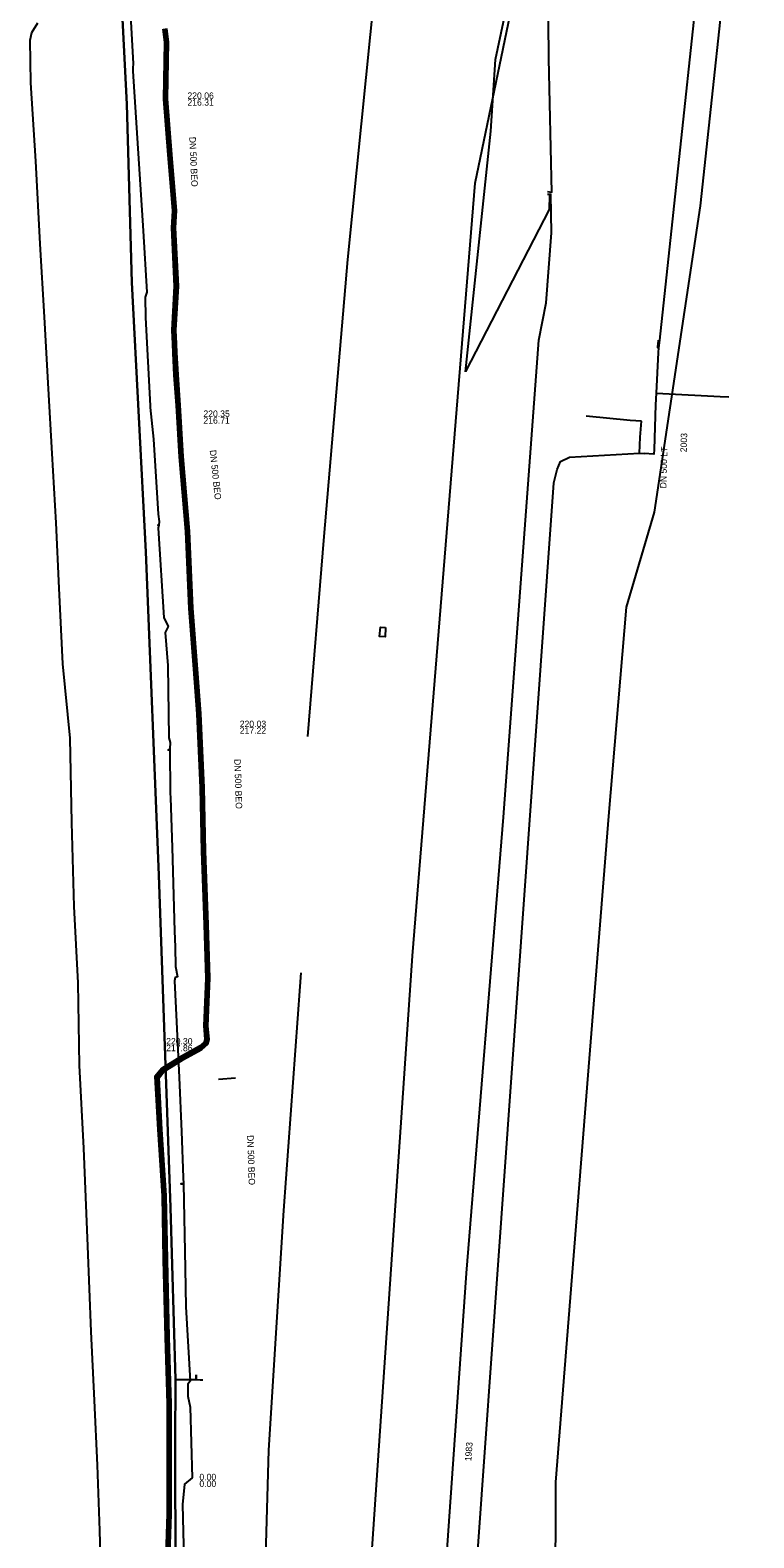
# Model space of a CAD drawing. Extents: x -599951 to -598963, y -1164095 to -1162939.
# Drawn here: x -599221.2 to -599131.5, y -1163894.1 to -1163707.4 of the extents above; entities that cross this region are included whole.
import ezdxf

# ---------------------------------------------------------------- set-up
doc = ezdxf.new("R2010")
doc.units = 0
for name, color, linetype in [('Level 1', 7, 'Continuous'), ('Level 3', 7, 'Continuous'), ('Vrstva 12', 7, 'Continuous'), ('Vrstva 13', 7, 'Continuous'), ('Vrstva 15', 7, 'Continuous'), ('Vrstva 42', 7, 'Continuous'), ('Vrstva 44', 7, 'Continuous'), ('Vrstva 55', 7, 'Continuous'), ('Vrstva 58', 7, 'Continuous'), ('Vrstva 9', 7, 'Continuous')]:
    doc.layers.add(name, color=color, linetype=linetype)

msp = doc.modelspace()

# ---------------------------------------------------------------- linework, layer by layer
at = {"layer": 'Level 1'}
for points in [[(-599173.8, -1163822.04), (-599166.01, -1163726.36), (-599144.8, -1163624.27), (-599116.33, -1163540.56), (-599088.36, -1163467.42), (-599053.62, -1163407.24), (-599018.44, -1163353.97), (-598979.36, -1163301.03), (-598963.215, -1163275.716)], [(-599189.994, -1164094.695), (-599188.19, -1164033.79), (-599173.8, -1163822.04)]]:
    msp.add_lwpolyline(points, dxfattribs=at)
at = {"layer": 'Level 3'}
msp.add_lwpolyline([(-599177.14, -1163781.39), (-599177.141, -1163781.419), (-599177.195, -1163782.524), (-599177.89, -1163782.49), (-599177.77, -1163781.36)], close=True, dxfattribs=at)
at = {"layer": 'Vrstva 13'}
for p, q in [((-599143.395, -1163746.537), (-599143.368, -1163746.3)), ((-599143.368, -1163746.3), (-599143.314, -1163745.805)), ((-599145.593, -1163757.802), (-599145.419, -1163755.84)), ((-599145.678, -1163759.782), (-599145.593, -1163757.802))]:
    msp.add_line(p, q, dxfattribs=at)
for points in [[(-599136.279, -1163681.357), (-599143.211, -1163745.819), (-599143.303, -1163746.751), (-599143.341, -1163747.337)], [(-599143.341, -1163747.337), (-599143.603, -1163752.362), (-599143.68, -1163753.83), (-599143.836, -1163759.328), (-599143.884, -1163759.926), (-599145.08, -1163759.83)], [(-599143.303, -1163746.751), (-599143.415, -1163746.741), (-599143.395, -1163746.537)], [(-599143.603, -1163752.362), (-599142.788, -1163752.405), (-599135.657, -1163752.781), (-599134.612, -1163752.841)], [(-599145.419, -1163755.84), (-599146.829, -1163755.755), (-599152.276, -1163755.203)], [(-599172.525, -1163991.426), (-599156.29, -1163763.465), (-599155.884, -1163761.839), (-599155.477, -1163760.823), (-599154.329, -1163760.314), (-599145.678, -1163759.782), (-599145.08, -1163759.83)]]:
    msp.add_lwpolyline(points, dxfattribs=at)
at = {"layer": 'Vrstva 42'}
for points in [[(-599211.757, -1163588.838), (-599211.66, -1163589.578), (-599212.89, -1163589.29), (-599214.35, -1163588.59), (-599214.49, -1163593.34), (-599213.28, -1163609.58), (-599212.1, -1163632.7), (-599211.89, -1163651.61), (-599210.7, -1163669.15), (-599209.68, -1163696.63), (-599210.04, -1163699.48), (-599209.19, -1163716.57), (-599208.58, -1163738.66), (-599206.82, -1163772.03), (-599205.21, -1163812.07), (-599203.78, -1163853.21), (-599203.16, -1163874.53), (-599200.61, -1163874.5), (-599200.591, -1163873.943)], [(-599211.757, -1163588.838), (-599211.66, -1163589.578), (-599212.89, -1163589.29), (-599214.35, -1163588.59), (-599214.49, -1163593.34), (-599213.28, -1163609.58), (-599212.1, -1163632.7), (-599211.89, -1163651.61), (-599210.7, -1163669.15), (-599209.68, -1163696.63), (-599210.04, -1163699.48), (-599209.19, -1163716.57), (-599208.58, -1163738.66), (-599206.82, -1163772.03), (-599205.21, -1163812.07), (-599203.78, -1163853.21), (-599203.16, -1163874.53), (-599200.61, -1163874.5), (-599200.591, -1163873.943)], [(-599203.14, -1163898.91), (-599203.18, -1163882.26), (-599203.16, -1163874.53), (-599203.78, -1163853.21), (-599205.21, -1163812.07), (-599206.82, -1163772.03), (-599208.58, -1163738.66), (-599209.19, -1163716.57), (-599210.04, -1163699.48)], [(-599210.04, -1163699.48), (-599209.19, -1163716.57), (-599208.58, -1163738.66), (-599206.82, -1163772.03), (-599205.21, -1163812.07), (-599203.78, -1163853.21), (-599203.16, -1163874.53), (-599203.18, -1163882.26), (-599203.14, -1163898.91)], [(-599203.14, -1163898.91), (-599203.18, -1163882.26), (-599203.16, -1163874.53), (-599203.78, -1163853.21), (-599205.21, -1163812.07), (-599206.82, -1163772.03), (-599208.58, -1163738.66), (-599209.19, -1163716.57), (-599210.04, -1163699.48)], [(-599203.14, -1163898.91), (-599203.18, -1163882.26), (-599203.16, -1163874.53), (-599203.78, -1163853.21), (-599205.21, -1163812.07), (-599206.82, -1163772.03), (-599208.58, -1163738.66), (-599209.19, -1163716.57), (-599210.04, -1163699.48)], [(-599203.14, -1163898.91), (-599203.18, -1163882.26), (-599203.16, -1163874.53), (-599203.78, -1163853.21), (-599205.21, -1163812.07), (-599206.82, -1163772.03), (-599208.58, -1163738.66), (-599209.19, -1163716.57), (-599210.04, -1163699.48)], [(-599203.16, -1163874.53), (-599200.61, -1163874.5), (-599200.08, -1163874.54), (-599199.769, -1163874.57)], [(-599200.591, -1163873.943), (-599200.61, -1163874.5)], [(-599200.591, -1163873.943), (-599200.61, -1163874.5), (-599200.08, -1163874.54), (-599199.769, -1163874.57)], [(-599200.591, -1163873.943), (-599200.61, -1163874.5), (-599200.08, -1163874.54), (-599199.769, -1163874.57)]]:
    msp.add_lwpolyline(points, dxfattribs=at)
at = {"layer": 'Vrstva 44'}
for points in [[(-599217.1, -1163785.88), (-599217.57, -1163776.52), (-599217.95, -1163768.43), (-599218.45, -1163759.85), (-599218.88, -1163751.83), (-599219.38, -1163742.94), (-599219.91, -1163733.87), (-599220.47, -1163723.63), (-599221.06, -1163713.95), (-599221.16, -1163708.67), (-599220.95, -1163707.7), (-599220.22, -1163706.51)], [(-599203.9, -1163897.455), (-599203.68, -1163891.155), (-599203.67, -1163884.615), (-599203.7, -1163877.515), (-599203.93, -1163869.275), (-599204.16, -1163859.695), (-599204.3, -1163851.735), (-599204.86, -1163843.545), (-599205.186, -1163837.148), (-599204.538, -1163836.373), (-599202.149, -1163834.903), (-599199.874, -1163833.644), (-599199.152, -1163832.999), (-599198.998, -1163832.408), (-599199.13, -1163830.726), (-599198.9, -1163824.834), (-599199.11, -1163818.164), (-599199.42, -1163809.084), (-599199.61, -1163801.244), (-599200.01, -1163792.048), (-599200.44, -1163786.528), (-599201.01, -1163779.008), (-599201.4, -1163769.445), (-599202.2, -1163760.215), (-599202.59, -1163753.855), (-599202.84, -1163750.115), (-599202.98, -1163747.341), (-599203.03, -1163746.251), (-599203.12, -1163744.551), (-599202.8, -1163739.11), (-599203.15, -1163731.91), (-599203.037, -1163729.752), (-599203.61, -1163722.807), (-599204.14, -1163715.924), (-599204, -1163708.859), (-599204.213, -1163707.192)], [(-599204.607, -1163707.268), (-599204.4, -1163708.881), (-599204.54, -1163715.936), (-599204.009, -1163722.839), (-599203.438, -1163729.758), (-599203.551, -1163731.909), (-599203.2, -1163739.119), (-599203.52, -1163744.549), (-599203.43, -1163746.27), (-599203.38, -1163747.36), (-599203.24, -1163750.142), (-599202.99, -1163753.883), (-599202.599, -1163760.245), (-599201.8, -1163769.473), (-599201.41, -1163779.032), (-599200.839, -1163786.555), (-599200.41, -1163792.072), (-599200.01, -1163801.257), (-599199.82, -1163809.096), (-599199.51, -1163818.177), (-599199.3, -1163824.839), (-599199.53, -1163830.734), (-599199.402, -1163832.372), (-599199.508, -1163832.781), (-599200.107, -1163833.316), (-599202.351, -1163834.557), (-599204.803, -1163836.067), (-599205.594, -1163837.012), (-599205.26, -1163843.562), (-599204.7, -1163851.749), (-599204.56, -1163859.704), (-599204.33, -1163869.285), (-599204.1, -1163877.523), (-599204.07, -1163884.62), (-599204.08, -1163891.156), (-599204.3, -1163897.453)], [(-599204.1, -1163897.447), (-599203.88, -1163891.151), (-599203.87, -1163884.615), (-599203.9, -1163877.518), (-599204.13, -1163869.28), (-599204.36, -1163859.699), (-599204.5, -1163851.743), (-599205.06, -1163843.557), (-599205.39, -1163837.08), (-599204.67, -1163836.22), (-599202.25, -1163834.73), (-599199.99, -1163833.48), (-599199.33, -1163832.89), (-599199.2, -1163832.39), (-599199.33, -1163830.73), (-599199.1, -1163824.833), (-599199.31, -1163818.171), (-599199.62, -1163809.09), (-599199.81, -1163801.251), (-599200.21, -1163792.061), (-599200.64, -1163786.544), (-599201.21, -1163779.029), (-599201.6, -1163769.458), (-599202.396, -1163760.278), (-599202.79, -1163753.868), (-599203.04, -1163750.127), (-599203.18, -1163747.35), (-599203.23, -1163746.261), (-599203.32, -1163744.55), (-599203, -1163739.109), (-599203.35, -1163731.92), (-599203.24, -1163729.76), (-599203.81, -1163722.82), (-599204.34, -1163715.93), (-599204.2, -1163708.87), (-599204.41, -1163707.23)], [(-599212.27, -1163902.45), (-599212.54, -1163893.23), (-599212.8, -1163885.13), (-599213.19, -1163877.11), (-599213.58, -1163868.57), (-599214.03, -1163858.01), (-599214.5, -1163845.85), (-599215.04, -1163835.65), (-599215.23, -1163825.41), (-599215.7, -1163815.95), (-599215.99, -1163805.53), (-599216.21, -1163795.08), (-599217.1, -1163785.88)]]:
    msp.add_lwpolyline(points, dxfattribs=at)
at = {"layer": 'Vrstva 55'}
for points in [[(-599175.395, -1163623.226), (-599162.201, -1163622.122), (-599162.465, -1163620.313), (-599163.569, -1163617.577), (-599163.745, -1163596.351), (-599163.392, -1163617.356), (-599162.156, -1163620.269), (-599161.81, -1163622.13), (-599160.56, -1163644.3), (-599158.79, -1163673), (-599157.055, -1163697.078), (-599156.945, -1163710.937), (-599156.578, -1163727.5), (-599157.054, -1163727.447)], [(-599167.231, -1163749.736), (-599164.09, -1163719.94), (-599163.502, -1163711.028), (-599161.82, -1163703.03), (-599149.662, -1163662.667), (-599149.9, -1163643.97), (-599149.72, -1163642.66), (-599141.225, -1163595.312), (-599149.72, -1163642.66), (-599150.889, -1163636.89), (-599151.042, -1163635.358), (-599152.176, -1163631.956), (-599152.636, -1163626.624), (-599153.984, -1163605.724)], [(-599186.765, -1163794.896), (-599184.748, -1163770.131), (-599181.786, -1163735.794), (-599176.721, -1163685.361), (-599176.249, -1163678.236), (-599175.133, -1163653.213), (-599174.919, -1163637.589), (-599175.457, -1163623.28)], [(-599162.057, -1164094.695), (-599165.35, -1164086.32), (-599166.73, -1164073.75), (-599165.047, -1164042.51), (-599160.24, -1164034.269), (-599157.836, -1164005.125), (-599157.45, -1163970.102), (-599156.162, -1163932.245), (-599156.04, -1163887.22), (-599152.39, -1163841.5), (-599149.466, -1163804.768), (-599147.296, -1163778.87), (-599143.812, -1163767.118), (-599138.093, -1163729.181), (-599134.088, -1163691.818), (-599133.543, -1163671.755), (-599132.377, -1163651.32), (-599127.82, -1163630.46), (-599126.99, -1163630.61)], [(-599208.92, -1163701.85), (-599208.39, -1163711.57), (-599208.43, -1163712.08), (-599208.44, -1163712.47), (-599207.178, -1163732.284), (-599206.69, -1163739.84), (-599206.9, -1163740.49), (-599206.85, -1163742.98), (-599206.299, -1163753.953), (-599206.29, -1163754.14), (-599205.86, -1163758.08), (-599205.31, -1163767.37), (-599205.16, -1163768.28), (-599205.2, -1163768.72), (-599205.35, -1163768.7), (-599205.2, -1163768.72), (-599205.31, -1163769.09), (-599204.59, -1163780.15), (-599204.07, -1163781.25), (-599204.43, -1163782.02), (-599204.12, -1163786.09), (-599203.97, -1163795.05), (-599203.81, -1163795.62), (-599203.87, -1163796.43), (-599204.08, -1163796.59), (-599203.87, -1163796.43), (-599203.797, -1163801.936), (-599203.79, -1163802.45), (-599203.596, -1163807.453), (-599203.55, -1163808.63), (-599203.262, -1163818.98), (-599203.208, -1163820.941), (-599203.14, -1163823.37), (-599202.89, -1163824.66), (-599203.2, -1163824.73), (-599203.29, -1163825.13), (-599203.031, -1163830.23), (-599202.68, -1163837.12), (-599202.417, -1163843.788), (-599202.19, -1163849.512), (-599202.16, -1163850.28), (-599202.484, -1163850.293), (-599202.16, -1163850.28), (-599201.974, -1163860.754), (-599201.89, -1163865.51), (-599201.32, -1163874.71), (-599201.61, -1163875.11), (-599201.64, -1163876.58), (-599201.34, -1163877.95), (-599201.09, -1163886.71), (-599202.02, -1163887.5), (-599202.27, -1163890.01), (-599202.1, -1163896.71)], [(-599176.967, -1164019.522), (-599176.964, -1164019.42), (-599175.409, -1163997.267), (-599174.614, -1163980.264), (-599171.61, -1163933.32), (-599169.898, -1163901.497), (-599167.091, -1163861.357), (-599162.51, -1163804.89), (-599158.142, -1163745.809), (-599157.22, -1163741.2), (-599156.59, -1163732.53), (-599156.662, -1163727.765), (-599157.054, -1163727.764)], [(-599156.831, -1163727.786), (-599156.866, -1163729.632), (-599167.232, -1163749.69)], [(-599201.77, -1164055.01), (-599201.73, -1164043.92), (-599199.084, -1164030.063), (-599198.94, -1164025.337), (-599197.401, -1163996.256), (-599196.422, -1163977.827), (-599195.864, -1163968.523), (-599194.12, -1163943.99), (-599192.431, -1163912.296), (-599191.573, -1163883.274), (-599189.739, -1163853.571), (-599187.709, -1163825.843), (-599187.581, -1163824.169)]]:
    msp.add_lwpolyline(points, dxfattribs=at)
at = {"layer": 'Vrstva 58'}
for points in [[(-599204, -1163897.464), (-599203.78, -1163891.162), (-599203.77, -1163884.62), (-599203.8, -1163877.518), (-599204.03, -1163869.277), (-599204.26, -1163859.698), (-599204.4, -1163851.736), (-599204.96, -1163843.544), (-599205.288, -1163837.114), (-599204.604, -1163836.297), (-599202.2, -1163834.816), (-599199.932, -1163833.562), (-599199.241, -1163832.944), (-599199.099, -1163832.399), (-599199.23, -1163830.728), (-599199, -1163824.84), (-599199.21, -1163818.167), (-599199.52, -1163809.087), (-599199.71, -1163801.247), (-599200.11, -1163792.054), (-599200.54, -1163786.532), (-599201.11, -1163779.014), (-599201.5, -1163769.454), (-599202.3, -1163760.223), (-599202.69, -1163753.864), (-599202.94, -1163750.124), (-599203.08, -1163747.346), (-599203.13, -1163746.256), (-599203.22, -1163744.55), (-599202.9, -1163739.121), (-599203.25, -1163731.915), (-599203.135, -1163729.763), (-599203.71, -1163722.814), (-599204.24, -1163715.927), (-599204.1, -1163708.865), (-599204.312, -1163707.211)], [(-599204.705, -1163707.287), (-599204.5, -1163708.886), (-599204.64, -1163715.939), (-599204.109, -1163722.847), (-599203.543, -1163729.773), (-599203.651, -1163731.909), (-599203.3, -1163739.118), (-599203.62, -1163744.549), (-599203.53, -1163746.275), (-599203.48, -1163747.365), (-599203.34, -1163750.148), (-599203.089, -1163753.889), (-599202.699, -1163760.252), (-599201.899, -1163769.479), (-599201.51, -1163779.037), (-599200.939, -1163786.563), (-599200.509, -1163792.078), (-599200.11, -1163801.26), (-599199.92, -1163809.099), (-599199.61, -1163818.18), (-599199.4, -1163824.839), (-599199.63, -1163830.736), (-599199.503, -1163832.363), (-599199.598, -1163832.727), (-599200.165, -1163833.234), (-599202.401, -1163834.471), (-599204.869, -1163835.99), (-599205.696, -1163836.978), (-599205.359, -1163843.568), (-599204.8, -1163851.753), (-599204.66, -1163859.706), (-599204.43, -1163869.288), (-599204.2, -1163877.525), (-599204.17, -1163884.62), (-599204.18, -1163891.155), (-599204.4, -1163897.449)], [(-599204.2, -1163897.456), (-599203.98, -1163891.158), (-599203.97, -1163884.62), (-599204, -1163877.522), (-599204.23, -1163869.283), (-599204.46, -1163859.702), (-599204.6, -1163851.744), (-599205.16, -1163843.556), (-599205.492, -1163837.046), (-599204.736, -1163836.143), (-599202.3, -1163834.644), (-599200.048, -1163833.398), (-599199.419, -1163832.836), (-599199.301, -1163832.381), (-599199.43, -1163830.732), (-599199.2, -1163824.84), (-599199.41, -1163818.173), (-599199.72, -1163809.093), (-599199.91, -1163801.253), (-599200.31, -1163792.066), (-599200.74, -1163786.548), (-599201.31, -1163779.026), (-599201.7, -1163769.466), (-599202.5, -1163760.237), (-599202.89, -1163753.876), (-599203.14, -1163750.136), (-599203.28, -1163747.355), (-599203.33, -1163746.266), (-599203.42, -1163744.55), (-599203.1, -1163739.119), (-599203.45, -1163731.925), (-599203.336, -1163729.752), (-599203.91, -1163722.826), (-599204.44, -1163715.933), (-599204.3, -1163708.875), (-599204.508, -1163707.249)]]:
    msp.add_lwpolyline(points, dxfattribs=at)
at = {"layer": 'Vrstva 9'}
msp.add_line((-599197.84, -1163837.31), (-599195.736, -1163837.171), dxfattribs=at)

# ---------------------------------------------------------------- texts
at = {"layer": 'Vrstva 12'}
for s, p in [('220.06', (-599201.677, -1163715.925)), ('216.31', (-599201.677, -1163716.757)), ('220.35', (-599199.698, -1163755.311)), ('216.71', (-599199.698, -1163756.143)), ('220.03', (-599195.194, -1163793.724)), ('217.22', (-599195.194, -1163794.556)), ('220.30', (-599204.313, -1163833.028)), ('217.86', (-599204.313, -1163833.86)), ('0.00', (-599200.192, -1163886.996)), ('0.00', (-599200.192, -1163887.828))]:
    msp.add_text(s, height=0.8, dxfattribs=at).set_placement(p)
for rotation, p in [(272.44143, (-599201.44, -1163720.637)), (276.05107, (-599198.919, -1163759.442)), (271.81118, (-599195.873, -1163797.687)), (271.86848, (-599194.28, -1163844.266))]:
    msp.add_text('DN 500 BEO', height=0.8, rotation=rotation, dxfattribs=at).set_placement(p)
at = {"layer": 'Vrstva 15'}
for s, rotation, p in [('2003', 88.35009, (-599139.816, -1163759.695)), ('DN 500 LT', 88.35009, (-599142.348, -1163764.168)), ('1983', 85.94367, (-599166.508, -1163884.666))]:
    msp.add_text(s, height=0.8, rotation=rotation, dxfattribs=at).set_placement(p)

doc.saveas('drawing.dxf')
